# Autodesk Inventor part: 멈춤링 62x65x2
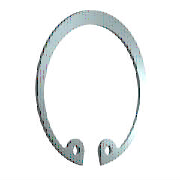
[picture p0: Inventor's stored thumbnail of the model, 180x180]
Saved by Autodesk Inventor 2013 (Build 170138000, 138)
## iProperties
IsCustomPart: 1
Created: 2012-02
Part Number: 멈춤링 62x65x2
Material: 강철, 연강
Description: 스프링 리테이닝 링
Document SubType Name: Modeling
Standard: JIS B 2804
Designer: mdu
Standards Organization: JIS
Language: ko-KR
Size Designation: 62x2
Categories: <MemberInstance><Categories><Category DisplayName="샤프트 부품" InternalName="7f7aeb1f-a693-4053-b835-cee3144e0d98" Mnemonic="SHFT"><Category DisplayName="써클립" Inter
Density: 1 g/cm^3
Author: mdu
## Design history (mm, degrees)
sketch "스케치1"
  geometry: L1 (0, 15.113)-(0, -73.177) reference; L2 (-45.5, 0)-(45.5, 0) reference; L3 (-4.964, 1.5)-(1.502, 1.5); L4 (0, -4)-(-5.307, -4); L5 (0, -31)-(-13.368, -60.623); L6 (-13.368, -60.623)-(-26.939, -54.499); L7 (-11.949, -57.479)-(-22.5, -52.717); L8 (-9.671, -58.507)-(-11.05, -61.564); L9 (9.671, -58.507)-(11.05, -61.564); C1 r 1.25 at (-11.949, -57.479); C2 r 1.25 at (11.949, -57.479); A1 r 28.375 centre (0, -32.375) between (16.406, -55.527) and (-16.406, -55.527); A2 r 32.5 centre (0, -31) between (11.05, -61.564) and (-11.05, -61.564); A3 r 2.5 centre (-11.949, -57.479) between (-9.671, -58.507) and (-13.455, -55.483); A4 r 2.5 centre (-14.96, -53.487) between (-16.406, -55.527) and (-13.455, -55.483); A5 r 2.5 centre (14.96, -53.487) between (13.455, -55.483) and (16.406, -55.527); A6 r 2.5 centre (11.949, -57.479) between (13.455, -55.483) and (9.671, -58.507); 3 further points
  constraints: 15 point on circle, 14 end point, 9 symmetric about line, 8 centre point, 6 tangent, 4 coincident, 4 point on line, 3 perpendicular, 1 parallel, 4 other
  dimensions: "d8" = 1.375 distance of A1.centre L5.start (= 0.25 x SRB1); "d38" = 5.5 distance between parallel lines of L4 L3 (= SRB1); "d39" = 31 distance from line of L5.start L2 (= 0.5 x WD); "d43" = 32.5 radius of A2 (= 0.5 x ND); "d45" = 3.45 distance between parallel lines of L7 L6 (= 0.5 x SRB2); "d46" = 2.5 radius of A4 (= SD5); "d47" = 11.05 distance from line of L1 L8.end (= 0.17 x ND); "d48" = 2.5 diameter of C1 (= SD5); "d49" = 2.5 radius of A3 (= SD5)
extrude "본체" new body sketch "스케치1" distance "d2" = 2 (= SD); taper "d3" = 0 deg
workaxis "Work Axis1"
workaxis "Work Axis2"
workplane "Work Plane1"
node "작업 평면2"
body "Solid1"
other parameters: "WD" = 62 [user parameter; used in 1 equation term], "SD" = 2 [user parameter; used in 1 equation term], "SRB1" = 5.5 [user parameter; used in 2 equation terms], "ND" = 65 [user parameter; used in 2 equation terms], "SRB2" = 6.9 [user parameter; used in 1 equation term], "SD5" = 2.5 [user parameter; used in 3 equation terms], "d50" = 0, "d51" = 0, "d52" = 0, "d53" = 0, "SD6" = 66.2 [user parameter], "WDMAX" = 62 (= NND) [user parameter], "NND" = 62 [user parameter; used in 1 equation term]
